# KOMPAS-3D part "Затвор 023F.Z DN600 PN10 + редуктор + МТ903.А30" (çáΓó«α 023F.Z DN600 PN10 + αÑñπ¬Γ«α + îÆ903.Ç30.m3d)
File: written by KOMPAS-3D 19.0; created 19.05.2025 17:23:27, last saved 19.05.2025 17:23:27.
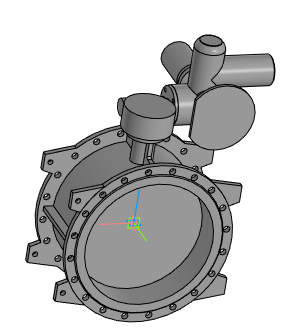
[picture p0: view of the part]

Document properties: Полное имя файла: Затвор 023F.Z DN600 PN10 + редуктор + МТ903.А30.a3d

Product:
- Part/product: Затвор 023F.Z DN600 PN10 + редуктор + МТ903.А30
    Масса: 554.248

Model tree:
1. Операция без истории:1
